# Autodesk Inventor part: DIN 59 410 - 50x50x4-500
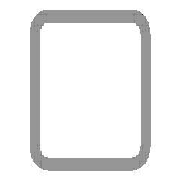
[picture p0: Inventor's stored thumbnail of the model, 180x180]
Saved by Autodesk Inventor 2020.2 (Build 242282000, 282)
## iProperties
Manager: www.cadconsulting.pl
Company: Fabian Stasiak CAD Consulting
Created: 2015-01
Part Number: DIN 59 410 - 50x50x4-500
Material: Stal, miękka
Description: Rurki stalowe o przekroju kwadratowym formowane na gorąco
Document SubType Name: Modellieren
Standard: DIN
Designer: F.Stasiak
Standards Organization: DIN
Language: pl-PL
Size Designation: 50x50x4
Categories: <MemberInstance><Categories><Category DisplayName="Kształtowniki konstrukcyjne" InternalName="089c4875-fa83-4c05-b084-43b9cc11f5ed" Mnemonic="GRDR"><CategoryPar
Stock Number: 50x50x4
Density: 7.85 g/cm^3
Appearance: Częściowo polerowana
Mass: 2781.62 g
Surface Area: 1785.63 cm^2
Volume: 354.346 cm^3
Catalog Web Link: www.expertbooks.pl
_CCFamilyMember: 40
_CCFamilyDisplayName: DIN 59410 (Kwadrat) - Rurki stalowe o przekroju kwadratowym formowane na gorąco
_FrameMemberDoc: Frame Member File
_Version: 15.0.0
_GetPNFromCC: 1
G_W: 50,000 mm
G_H: 50,000 mm
G_L: 500,000 mm
+E57B3224-DE9D-49F7-A1D7-BCD5112B5307+CUTDETAIL4: Wytnij
+6F3E057D-F9C7-47CB-A42A-703FA4CD32E1+CUTDETAIL5: Wytnij
IsCustomPart: 1
Author: F.Stasiak
Subject: Zbiór ćwiczeń. Autodesk Inventor 2020. Kurs Professional
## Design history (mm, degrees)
node "Płaszczyzna początkowa"
node "Płaszczyzna końcowa"
sketch "Szkic"
  geometry: L1 (-17, 25)-(17, 25); L2 (25, 17)-(25, -17); L3 (17, -25)-(-17, -25); L4 (-25, -17)-(-25, 17); L5 (-37.32, 0)-(37.32, 0) reference; L6 (0, -37.32)-(0, 37.32) reference; L7 (-17, 21)-(17, 21); L8 (21, 17)-(21, -17); L9 (17, -21)-(-17, -21); L10 (-21, -17)-(-21, 17); A1 r 8 centre (-17, 17) between (-17, 25) and (-25, 17); A2 r 8 centre (17, 17) between (25, 17) and (17, 25); A3 r 8 centre (17, -17) between (17, -25) and (25, -17); A4 r 8 centre (-17, -17) between (-25, -17) and (-17, -25); A5 r 4 centre (-17, 17) between (-17, 21) and (-21, 17); A6 r 4 centre (17, 17) between (21, 17) and (17, 21); A7 r 4 centre (17, -17) between (17, -21) and (21, -17); A8 r 4 centre (-17, -17) between (-21, -17) and (-17, -21); 3 further points
  constraints: 16 end point, 16 point on circle, 8 centre point, 8 tangent, 6 point on line, 4 parallel, 3 equal radius, 3 perpendicular, 1 horizontal, 7 other
  dimensions: "b" = 50 distance of point (-25, 25) point (25, 25); "msp_r" = 8 radius of A1 (= 2 x ParT); "d8" = 25 distance between parallel lines of L4 L6 (= d9); "d9" = 25 distance between parallel lines of L3 L5 (= 0.5 x b); "d10" = 4 distance between parallel lines of L3 L9 (= ParT)
extrude "Bryła" new body sketch "Szkic" taper "d4" = 0 deg; stored distance "NLG" = 10
node "Driven Length"
  sketch "Sketch2"
    geometry: L1 (0, 0)-(10, 0) reference
    constraints: 2 end point, 1 horizontal
  workplane "Work Plane3"
  sketch "Sketch3"
    geometry: L1 (-2, -25)-(12, -25) reference; L2 (-2, 475)-(12, 475) reference
    dimensions: "d14" = 500 distance between parallel lines of L1 L2 (derived)
node "Płaszczyzna konstrukcyjna7"
feature "Podział4"
node "Płaszczyzna konstrukcyjna8"
feature "Podział5"
body "Solid1"
other parameters: "ParT" = 4, "G_OFFSET_START" = 25 [user parameter; used in 1 equation term], "G_OFFSET_END" = -25 [user parameter; used in 1 equation term], "d11" = -25 (= -G_OFFSET_START), "d12" = 475 (= G_OFFSET_END + B_L), "G_L" = 500 (= d14) [user parameter], "d13" = 90 deg
